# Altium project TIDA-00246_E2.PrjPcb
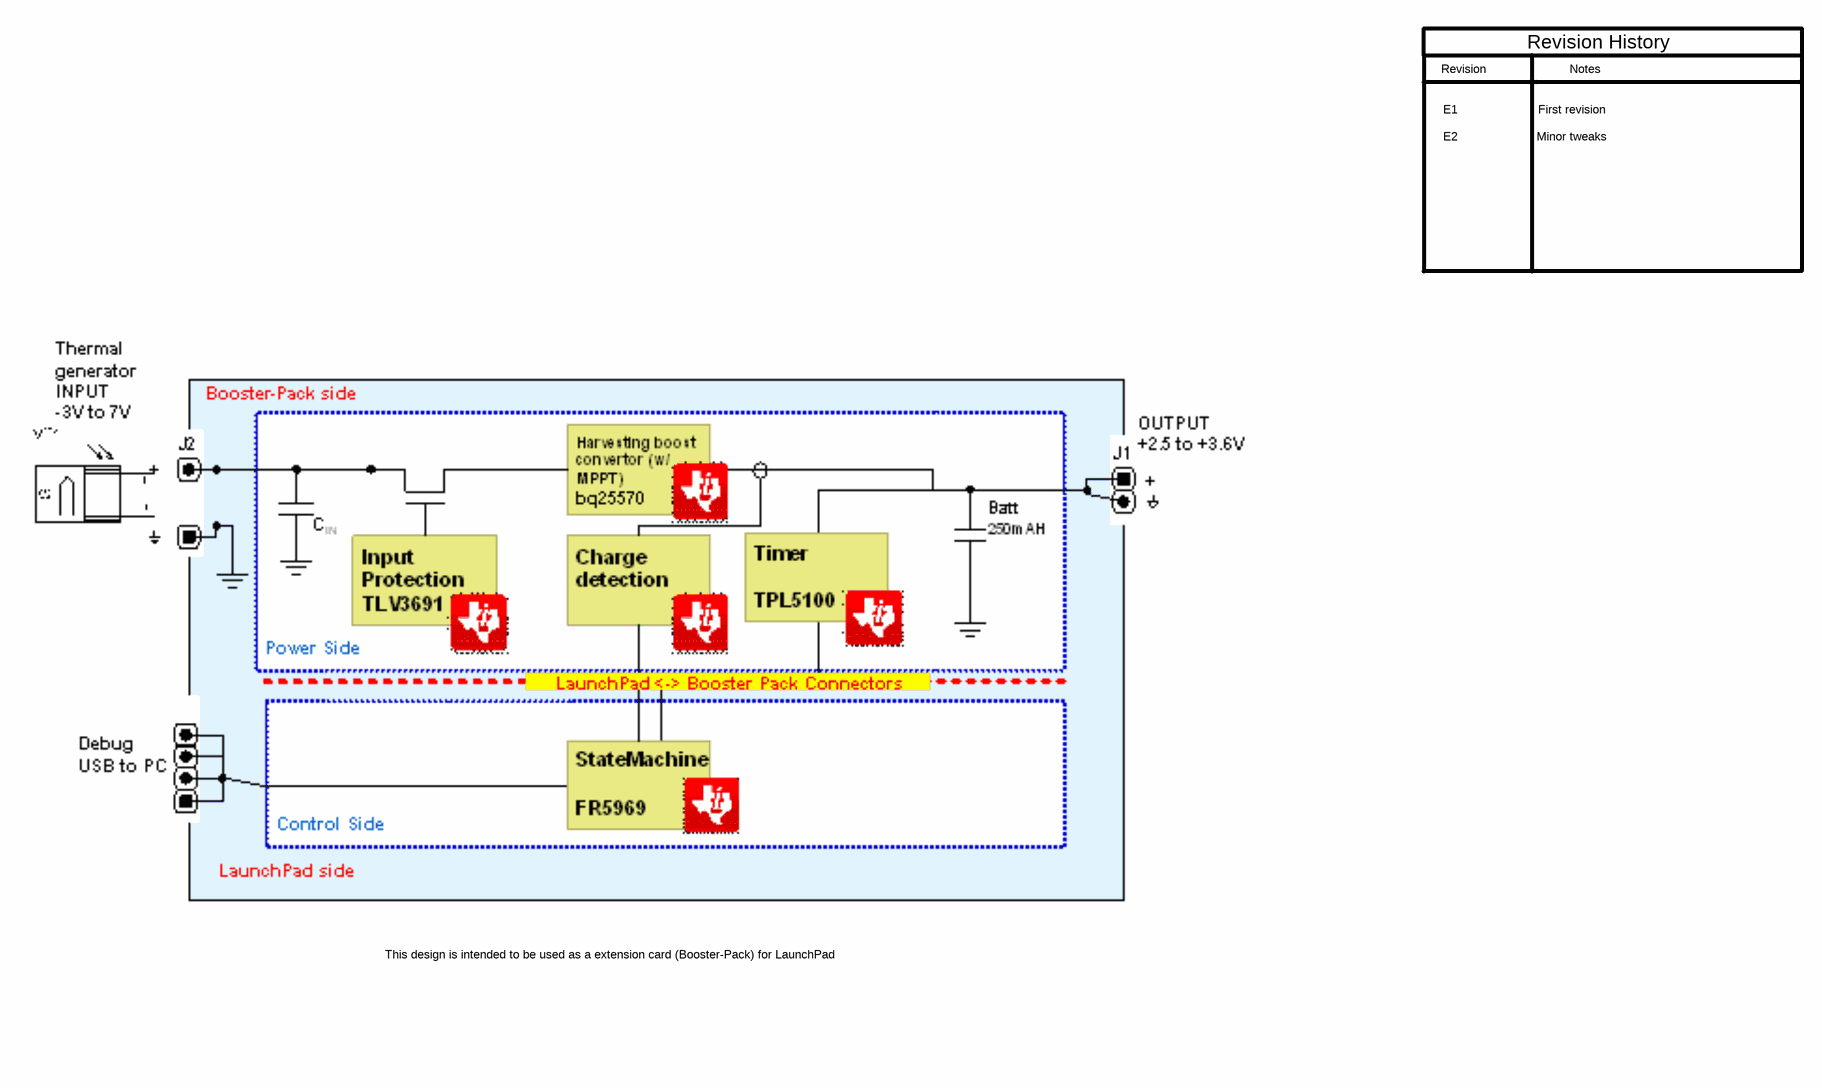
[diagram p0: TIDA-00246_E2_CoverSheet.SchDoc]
TID: TIDA-00246; TechSupport: http://www.ti.com/support; SCH_Rev: E2; PRJ_Title: Generic Energy Harvester Adapter Module for Marlow PowerStrap; PRJ_Number: TIDA-00246; PRJ_Engineer: M. Chevrier; PRJ_Customer: Public Release; PCB_Rev: E2; PCB_Layout: E2: MCV - E1:GCD/KLAK; EVM_Orderable: N/A; CopyrightYear: 2014
4 sheets, 75 parts. Net scope: flat (ports and power ports of the same name join across sheets).
Board file: TIDA-00246_E2_TID.PcbDoc
Sheets:
  TIDA-00246_E2_CoverSheet.SchDoc
  TIDA-00246_E2_Power.SchDoc
  TIDA-00246_E2_BoosterPack.SchDoc
  TIDA-00246_E2_TID_Hardware.SchDoc

## Sheet TIDA-00246_E2_CoverSheet.SchDoc
size 431 x 279 mm; Date: Not shown in title block; ApprovedBy: Not shown in title block; CheckedBy: Not shown in title block; Author: Not shown in title block; CompanyName: Not shown in title block; Engineer: Not shown in title block; Organization: Not shown in title block; Address1: Not shown in title block; Address2: Not shown in title block; Address3: Not shown in title block; Address4: Not shown in title block; DocumentNumber: 1; Revision: Use project parameter SCH_Rev; SheetNumber: 1; SheetTotal: 4; PageSetup: Record=PageOptions¦CenterHorizontal=True¦CenterVertical=True¦PrintScale=1.00¦XCorrection=1.00¦YCorrection=1.00¦PrintKind=0¦BorderSize=5000000¦LeftOffset=0¦BottomOffset=0¦Orientation=2¦PaperLength=1000¦PaperWidth=1000¦Scale=100¦PaperSource=15¦PrintQuality=-3¦MediaType=1¦DitherType=10¦PrintScaleMode=1¦PaperKind=11x17¦PaperIndex=3

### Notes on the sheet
- Revision
- Notes
- Revision History
- E1
- E2
- First revision
- Minor tweaks
- This design is intended to be used as a extension card (Booster-Pack) for LaunchPad

## Sheet TIDA-00246_E2_Power.SchDoc
size 431 x 279 mm; Date: Not shown in title block; ApprovedBy: Not shown in title block; CheckedBy: Not shown in title block; Author: Not shown in title block; CompanyName: Not shown in title block; Engineer: Not shown in title block; Organization: Not shown in title block; Address1: Not shown in title block; Address2: Not shown in title block; Address3: Not shown in title block; Address4: Not shown in title block; DocumentNumber: 2; Revision: Use project parameter SCH_Rev; SheetNumber: 2; SheetTotal: 4; PageSetup: Record=PageOptions¦CenterHorizontal=True¦CenterVertical=True¦PrintScale=1.00¦XCorrection=1.00¦YCorrection=1.00¦PrintKind=0¦BorderSize=5000000¦LeftOffset=0¦BottomOffset=0¦Orientation=2¦PaperLength=1000¦PaperWidth=1000¦Scale=100¦PaperSource=15¦PrintQuality=600¦MediaType=1¦DitherType=10¦PaperKind=Letter¦PrintScaleMode=1
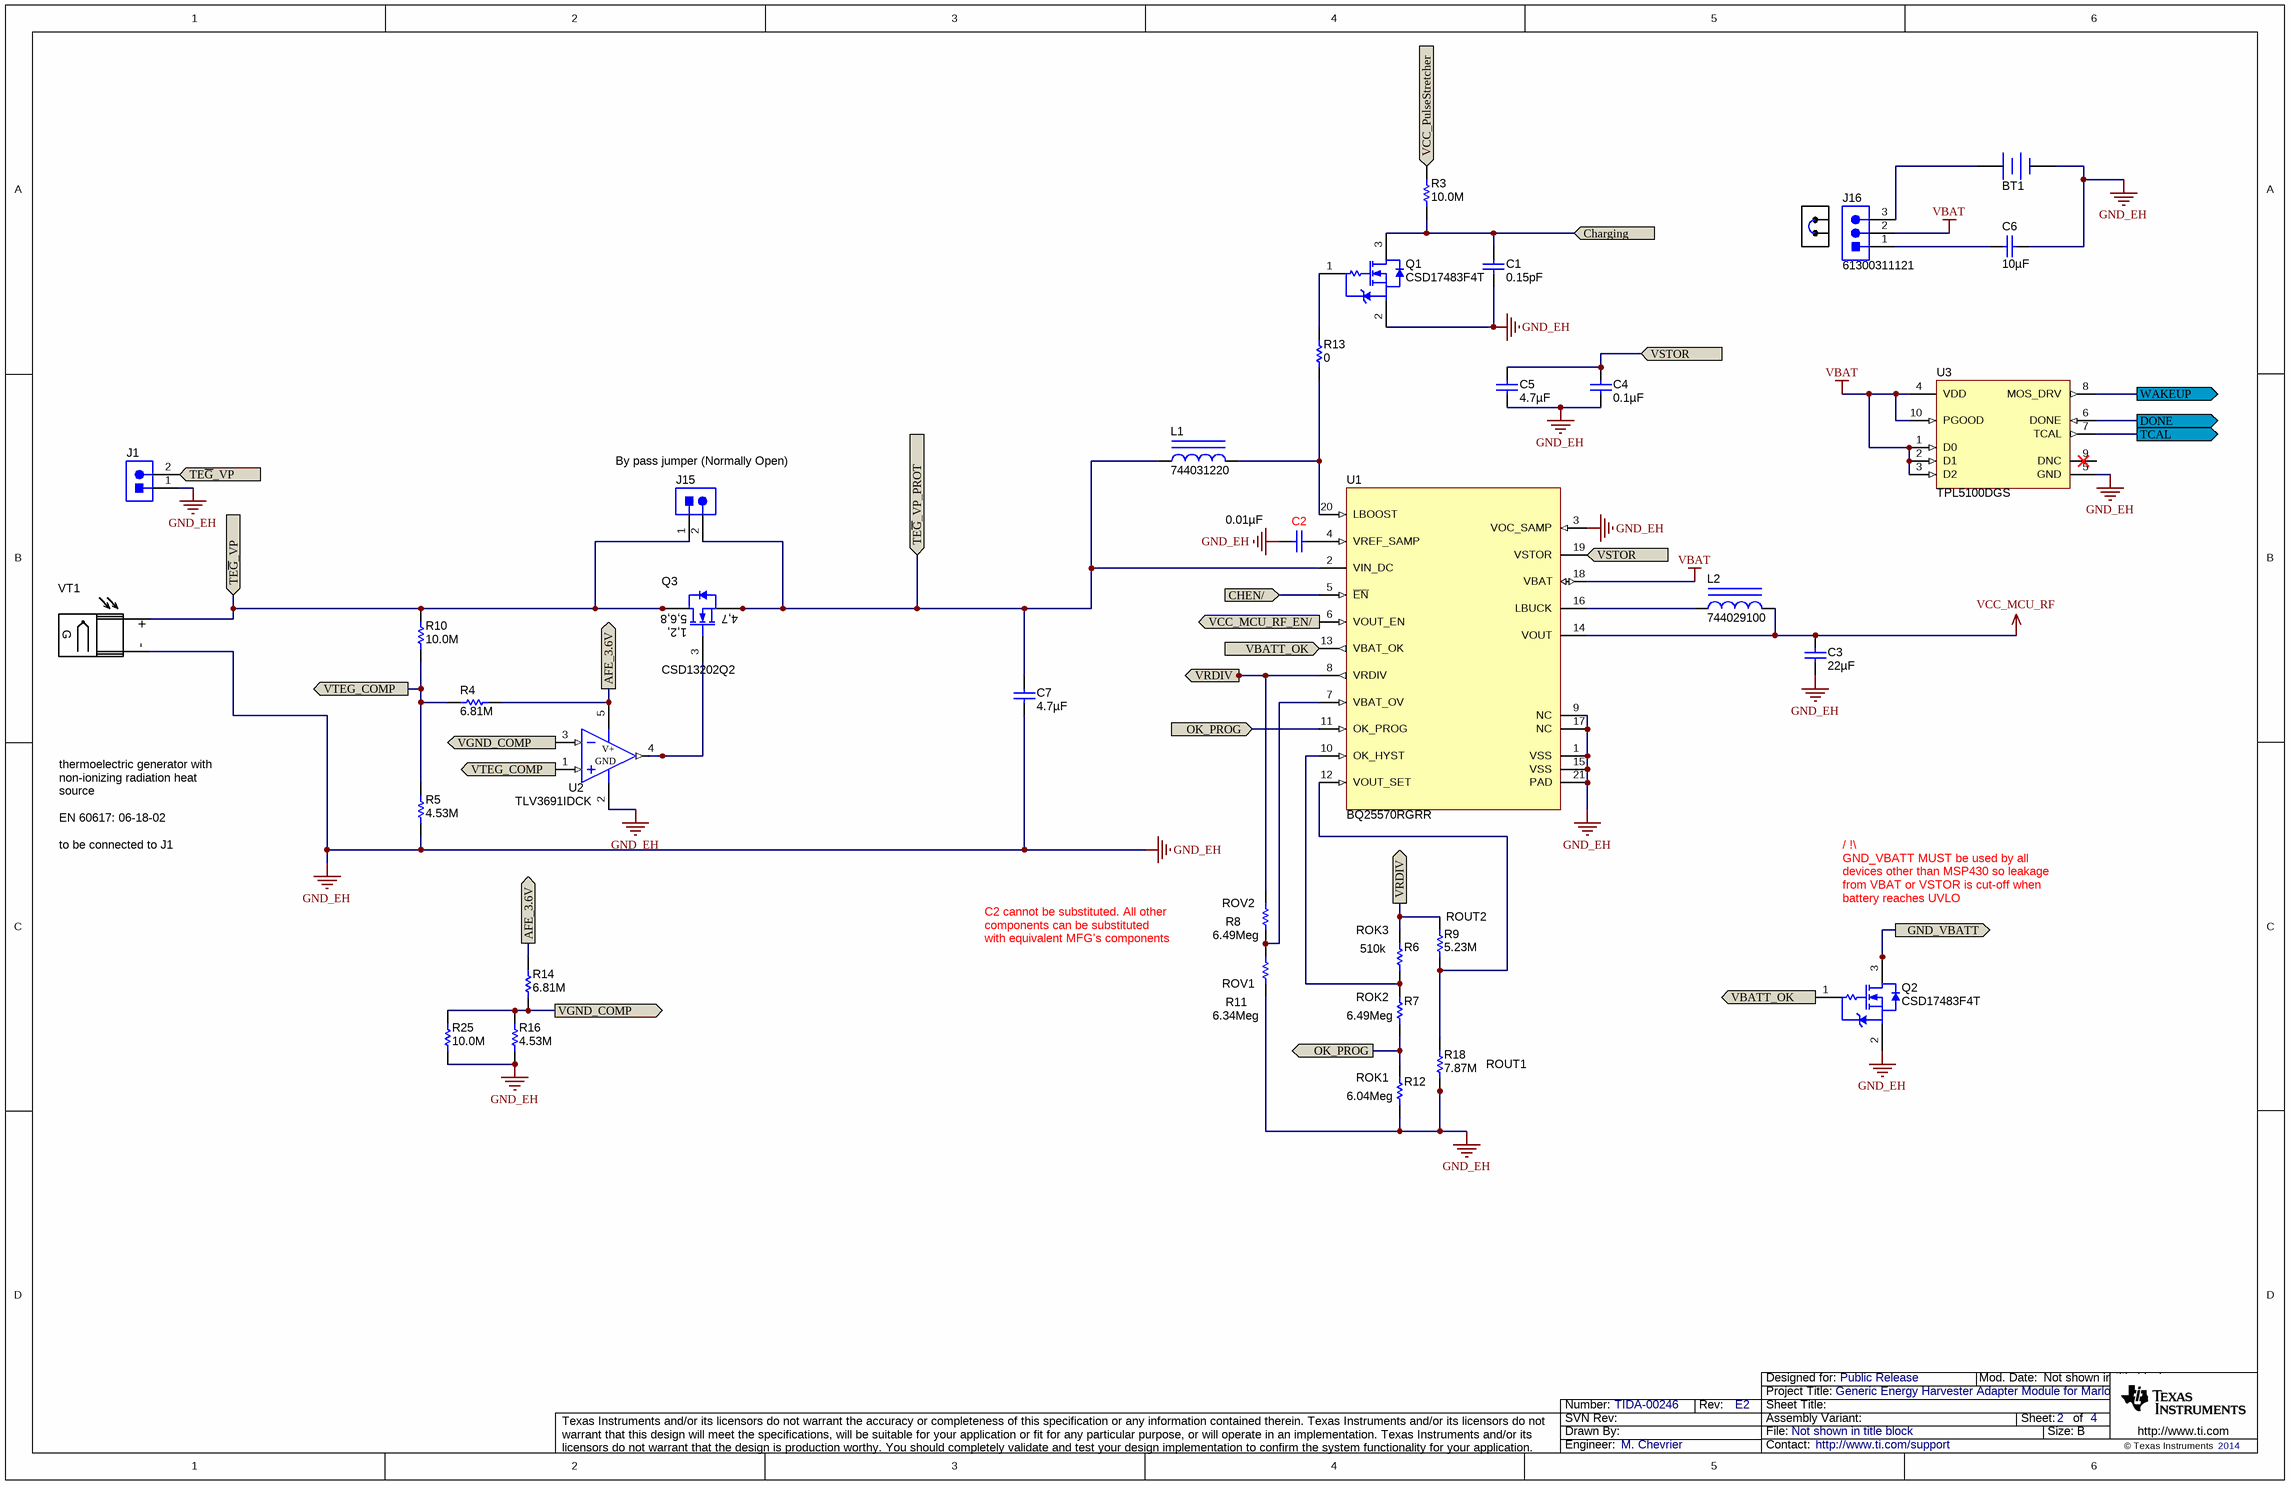
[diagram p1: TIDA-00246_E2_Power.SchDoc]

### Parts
BT1  HLC-1550A/TP  [Tadiran_HLC-1550A_TP]  (value not drawn)
C1  ValueDisplayed: 0.15pF  [0402_70]  (hidden comment: C04ULR15D-6SN-X0T)
C2  ValueDisplayed: 0.01µF  [0603]  (hidden comment: GRM188R71H103KA01D)
C3  ValueDisplayed: 22µF  [0805_HV]  (hidden comment: JMK212BJ226MG-T)
C4  ValueDisplayed: 0.1µF  [0603]  (hidden comment: 06033D104KAT2A)
C5  ValueDisplayed: 4.7µF  [0805_HV]  (hidden comment: LMK212B7475KG-T)
C6  ValueDisplayed: 10µF  [1210]  (hidden comment: 1210YD106KAT2A)
C7  ValueDisplayed: 4.7µF  [0805_HV]  (hidden comment: LMK212B7475KG-T)
J1  61300211121  [WURTH_61300211121]  (value not drawn)
J15  61300211121  [WURTH_61300211121]  (value not drawn)
J16  61300311121  [WURTH_61300311121]
L1  744031220  [WE-TPC-S]
L2  744029100  [WE-TPC_2813]
Q1  CSD17483F4T  [YJC0003A]
Q2  CSD17483F4T  [YJC0003A]
Q3  CSD13202Q2  [TRANS_NexFET_Q2]
R3  ValueDisplayed: 10.0M  [1206]  (hidden comment: CRCW120610M0FKEA)
R4  ValueDisplayed: 6.81M  [1206]  (hidden comment: CRCW12066M81FKEA)
R5  ValueDisplayed: 4.53M  [1206]  (hidden comment: CRCW12064M53FKEA)
R6  value 510k  [0603]  (hidden comment: CRCW0603510KJNEA)
R7  value 6.49Meg  [0603]  (hidden comment: CRCW06036M49FKEA)
R8  value 6.49Meg  [0603]  (hidden comment: CRCW06036M49FKEA)
R9  ValueDisplayed: 5.23M  [0805_HV]  (hidden comment: CRCW08055M23FKEA)
R10  ValueDisplayed: 10.0M  [1206]  (hidden comment: CRCW120610M0FKEA)
R11  value 6.34Meg  [0603]  (hidden comment: CRCW06036M34FKEA)
R12  value 6.04Meg  [0603]  (hidden comment: CRCW06036M04FKEA)
R13  ValueDisplayed: 0  [0805_HV]  (hidden comment: CRCW08050000Z0EA)
R14  ValueDisplayed: 6.81M  [1206]  (hidden comment: CRCW12066M81FKEA)
R16  ValueDisplayed: 4.53M  [1206]  (hidden comment: CRCW12064M53FKEA)
R18  ValueDisplayed: 7.87M  [1206]  (hidden comment: CRCW12067M87FKEA)
R25  ValueDisplayed: 10.0M  [1206]  (hidden comment: CRCW120610M0FKEA)
SH-J11  969102-0000-DA  [SNT-100-BK-G]  (value not drawn)
U1  BQ25570RGRR  [RGR0020A]
U2  TLV3691IDCK  [DCK0005A_N]
U3  TPL5100DGS  [DGS0010A_N]
VT1  N/A  (value not drawn)

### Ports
AFE_3.6V, Charging, CHEN/ (in), DONE (out), GND_VBATT (out), OK_PROG (in), OK_PROG (out), TCAL (out), TE~{G}_VP, TE~{G}_VP_PROT, VBATT_OK (out), VCC_MCU_RF_EN/ (in), VCC_PulseStretcher, VGND_COMP (out), VRDIV, VSTOR, VTEG_COMP (out), WAKEUP (out)

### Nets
GND_EH: BT1.2(-) C1.2 C2.1 C3.2 C4.2 C5.2 C6.1 C7.2 J1.1 Q1.2(S) Q2.2(S) R5.1 R11.2 R12.2 R16.1 R18.1 R25.1 U1.1(VSS) U1.3(VOC_SAMP) U1.9(NC) U1.15(VSS) U1.17(NC) U1.21(PAD) U2.2(GND) U3.5(GND) VT1.2(-)
VBAT: J16.2 U1.18(VBAT) U3.1(D0) U3.2(D1) U3.3(D2) U3.4(VDD) U3.10(PGOOD)
VCC_MCU_RF: C3.1 L2.1 U1.14(VOUT)
AFE_3.6V: R4.2 R14.2 U2.5(V+) ; port AFE_3.6V
Charging: C1.1 Q1.3(D) R3.1 ; port Charging
CHEN/: U1.5(~{EN}) ; port CHEN/
DONE: U3.6(DONE) ; port DONE
GND_VBATT: Q2.3(D) ; port GND_VBATT
OK_PROG: R7.1 R12.1 U1.11(OK_PROG) ; port OK_PROG
TCAL: U3.7(TCAL) ; port TCAL
TE~{G}_VP: J1.2 J15.1 Q3.1(D) Q3.2(D) Q3.5(D) Q3.6(D) Q3.8(D) R10.2 VT1.1(+) ; port TE~{G}_VP
TE~{G}_VP_PROT: C7.1 J15.2 L1.1 Q3.4(S) Q3.7(S) U1.2(VIN_DC) ; port TE~{G}_VP_PROT
VBATT_OK: Q2.1(G) U1.13(VBAT_OK) ; port VBATT_OK
VCC_MCU_RF_EN/: U1.6(VOUT_EN) ; port VCC_MCU_RF_EN/
VCC_PulseStretcher: R3.2 ; port VCC_PulseStretcher
VGND_COMP: R14.1 R16.2 R25.2 U2.3(IN-) ; port VGND_COMP
VRDIV: R6.2 R8.2 R9.2 U1.8(VRDIV) ; port VRDIV
VSTOR: C4.1 C5.1 U1.19(VSTOR) ; port VSTOR
VTEG_COMP: R4.1 R5.2 R10.1 U2.1(IN+) ; port VTEG_COMP
WAKEUP: U3.8(MOS_DRV) ; port WAKEUP
NetBT1_1: BT1.1(+) J16.3
NetC2_2: C2.2 U1.4(VREF_SAMP)
NetC6_2: C6.2 J16.1
NetL1_2: L1.2 R13.1 U1.20(LBOOST)
NetL2_2: L2.2 U1.16(LBUCK)
NetQ1_1: Q1.1(G) R13.2
NetQ3_3: Q3.3(G) U2.4(OUT)
NetR6_1: R6.1 R7.2 U1.10(OK_HYST)
NetR8_1: R8.1 R11.1 U1.7(VBAT_OV)
NetR9_1: R9.1 R18.2 U1.12(VOUT_SET)

Not connected (* = marked no-connect by the designer): U3 9(DNC)

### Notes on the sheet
- (near J15) By pass jumper (Normally Open)
- thermoelectric generator with non-ionizing radiation heat source
  EN 60617: 06-18-02
  to be connected to J1
- (near R8) ROV2
- / !\
  GND_VBATT MUST be used by all devices other than MSP430 so leakage from VBAT or VSTOR is cut-off when battery reaches UVLO
- C2 cannot be substituted. All other components can be substituted with equivalent MFG's components
- (near R6) ROK3
- (near R9) ROUT2
- (near R11) ROV1
- ROK2
- (near R12) ROK1
- (near R18) ROUT1

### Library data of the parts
BT1 = HLC-1550A/TP: Battery, 3.95 V, Axial, TH; Manufacturer: Tadiran Batteries
C1 = C04ULR15D-6SN-X0T: CAP, CERM, 0.15 pF, 200 V, +/- %, X7R, 0402; Manufacturer: Knowles Accoustics; Polarized: N; CompType: Capacitor; Value: 0.15pF; U/M: EA; Cap_F: 0.00000000000015; Value1: Unknown; VDC_V: 200; Value2: 200V; TaMin_C: -55; TaMax_C: 125; Cap_Case: 0402
C2 = GRM188R71H103KA01D: CAP, CERM, 0.01uF, 50V, +/-10%, X7R, 0603; Manufacturer: MuRata; Polarized: N; CompType: Capacitor; U/M: EA; Cap_F: 0.00000001; Tolerance_%: 10; Value1: Unknown; VDC_V: 50; TaMin_C: -55; TaMax_C: 125
C3 = JMK212BJ226MG-T: CAP, CERM, 22uF, 6.3V, +/-20%, X5R, 0805; Manufacturer: Taiyo Yuden; Polarized: N; CompType: Capacitor; U/M: EA; Cap_F: 0.000022; Tolerance_%: 20; Value1: Unknown; VDC_V: 6.3; TaMin_C: -55; TaMax_C: 85; Cap_Case: 0805
C4 = 06033D104KAT2A: CAP, CERM, 0.1uF, 25V, +/-10%, X5R, 0603; Manufacturer: AVX; Polarized: N; CompType: Capacitor; U/M: EA; Cap_F: 0.0000001; Tolerance_%: 10; ESR_Ohm: 0.048; Value1: 0.048 ohm; VDC_V: 25; IRMS_A: 0.53; TaMin_C: -55; TaMax_C: 85
C5 C7 = LMK212B7475KG-T: CAP, CERM, 4.7uF, 10V, +/-10%, X7R, 0805; Manufacturer: Taiyo Yuden; Polarized: N; CompType: Capacitor; U/M: EA; Cap_F: 0.0000047; Tolerance_%: 10; Value1: Unknown; TaMin_C: -55; TaMax_C: 125; Cap_Case: 0805
C6 = 1210YD106KAT2A: CAP, CERM, 10 µF, 16 V, +/- 10%, X5R, 1210; Manufacturer: AVX; Polarized: N; CompType: Capacitor; Value: 10uF; U/M: EA; Cap_F: 0.00001; Tolerance_%: 10; Value1: Unknown; VDC_V: 16; Value2: 16V; TaMin_C: -55; TaMax_C: 85
J1 J15 = 61300211121: Header, 2.54 mm, 2x1, Gold, TH; Manufacturer: Wurth Elektronik eiSos; SymbolCreator: a0412235; U/M: EA
J16 = 61300311121: Header, 2.54 mm, 3x1, Gold, TH; Manufacturer: Wurth Elektronik eiSos; SymbolCreator: a0799628; U/M: EA
L1 = 744031220: Inductor, Shielded Drum Core, Ferrite, 22 µH, 0.36 A, 0.41 ohm, SMD; Manufacturer: Wurth Elektronik eiSos; Value: 22uH; Ind_H: 22.0E-6; ValueDisplayed: 22µH; Imax_A: 0.36; Irms: 0.51A @ 30C rise; Isat: 0.36A @ 35% inductance drop; DCR_ohm: 0.41; Value2: 0.36A
L2 = 744029100: Inductor, Shielded Drum Core, Ferrite, 10 µH, 0.5 A, 0.39 ohm, SMD; Manufacturer: Wurth Elektronik eiSos; Value: 10uH; Ind_H: 10.0E-6; ValueDisplayed: 10µH; Imax_A: 0.5; Irms: 0.75A @ 40C rise; Isat: 0.5A @ 35% inductance drop; DCR_ohm: 0.39; Value2: 0.5A
Q1 Q2 = CSD17483F4T: MOSFET, N/P-CH, 30 V, 1.5 A, 1.0x0.35x0.6mm; Manufacturer: Texas Instruments; Alternate Manufacturer: None; SymbolCreator: a0411947; U/M: EA; ChType: N; Value: 30V; VdsMax_V: 30; Value1: 0.2 ohm; Rdson45_ohm: 0.2; Value2: 1.01 nC; QgTyp_nC: 1.01; Vgs_V: 12; IdsMax_A: 1.5
Q3 = CSD13202Q2: MOSFET, N-CH, 12 V, 14.4 A, SON 2x2mm; Manufacturer: Texas Instruments; Alternate Manufacturer: None; U/M: EA; ChType: N; Value: 12V; VdsMax_V: 12; Value1: 0.0093 ohm; Rdson45_ohm: 0.0093; Value2: 5.1 nC; QgTyp_nC: 5.1; Vgs_V: 8; IdsMax_A: 14.4
R3 R10 R25 = CRCW120610M0FKEA: RES, 10.0 M, 1%, 0.25 W, 1206; Manufacturer: Vishay-Dale; CompType: Resistor; Value: 10.0Meg; Res_ohm: 10000000; Value_Code: 10M0; Tolerance_%: 1; Power_W: 0.25; Value2: 0.25W; VDC_V: 200; TempCo: 100 ppm/C; EIA_Code: E96; U/M: EA
R4 R14 = CRCW12066M81FKEA: RES, 6.81 M, 1%, 0.25 W, 1206; Manufacturer: Vishay-Dale; CompType: Resistor; Value: 6.81Meg; Res_ohm: 6810000; Value_Code: 6M81; Tolerance_%: 1; Power_W: 0.25; Value2: 0.25W; VDC_V: 200; TempCo: 100 ppm/C; EIA_Code: E96; U/M: EA
R5 R16 = CRCW12064M53FKEA: RES, 4.53 M, 1%, 0.25 W, 1206; Manufacturer: Vishay-Dale; CompType: Resistor; Value: 4.53Meg; Res_ohm: 4530000; Value_Code: 4M53; Tolerance_%: 1; Power_W: 0.25; Value2: 0.25W; VDC_V: 200; TempCo: 100 ppm/C; EIA_Code: E96; U/M: EA
R6 = CRCW0603510KJNEA: RES, 510k ohm, 5%, 0.1W, 0603; Manufacturer: Vishay-Dale; CompType: Resistor; Res_ohm: 510000; Tolerance_%: 5; Power_W: 0.1; VDC_V: 75; TempCo: 200 ppm/C; EIA_Code: E24; U/M: EA
R7 R8 = CRCW06036M49FKEA: RES, 6.49Meg ohm, 1%, 0.1W, 0603; Manufacturer: Vishay-Dale; CompType: Resistor; Res_ohm: 6490000; Value_Code: 6M49; Tolerance_%: 1; Power_W: 0.1; VDC_V: 75; TempCo: 100 ppm/C; EIA_Code: E96; U/M: EA
R9 = CRCW08055M23FKEA: RES, 5.23 M, 1%, 0.125 W, 0805; Manufacturer: Vishay-Dale; CompType: Resistor; Value: 5.23Meg; Res_ohm: 5230000; Value_Code: 5M23; Tolerance_%: 1; Power_W: 0.125; Value2: 0.125W; VDC_V: 150; TempCo: 100 ppm/C; EIA_Code: E96; U/M: EA
R11 = CRCW06036M34FKEA: RES, 6.34Meg ohm, 1%, 0.1W, 0603; Manufacturer: Vishay-Dale; CompType: Resistor; Res_ohm: 6340000; Value_Code: 6M34; Tolerance_%: 1; Power_W: 0.1; VDC_V: 75; TempCo: 100 ppm/C; EIA_Code: E96; U/M: EA
R12 = CRCW06036M04FKEA: RES, 6.04Meg ohm, 1%, 0.1W, 0603; Manufacturer: Vishay-Dale; CompType: Resistor; Res_ohm: 6040000; Value_Code: 6M04; Tolerance_%: 1; Power_W: 0.1; VDC_V: 75; TempCo: 100 ppm/C; EIA_Code: E96; U/M: EA
R13 = CRCW08050000Z0EA: RES, 0, 5%, 0.125 W, 0805; Manufacturer: Vishay-Dale; CompType: Resistor; Value: 0; Value_Code: 0000; Tolerance_%: 5; Power_W: 0.125; Value2: 0.125W; VDC_V: 150; TempCo: 200 ppm/C; EIA_Code: E24; U/M: EA
R18 = CRCW12067M87FKEA: RES, 7.87 M, 1%, 0.25 W, 1206; Manufacturer: Vishay-Dale; CompType: Resistor; Value: 7.87Meg; Res_ohm: 7870000; Value_Code: 7M87; Tolerance_%: 1; Power_W: 0.25; Value2: 0.25W; VDC_V: 200; TempCo: 100 ppm/C; EIA_Code: E96; U/M: EA
SH-J11 = 969102-0000-DA: Shunt, 100mil, Gold plated, Black; Manufacturer: 3M; Alternate Manufacturer: Samtec; Value: 1x2; Note: You can "mate" this to a header by matching the designator.  i.e. use SH-J3 for header J3
U1 = BQ25570RGRR: Ultra Low Power Harvester Power Management IC with Boost Charger, and Nano-Powered Buck Converter, RGR0020A; Alternate PartNumber: BQ25570RGRT; Manufacturer: Texas Instruments; SymbolCreator: a0412235; U/M: EA
U2 = TLV3691IDCK: 0.9-V to 6.5-V, Nanopower Comparator, DCK0005A; Manufacturer: Texas Instruments; SymbolCreator: OpAmp IC; CompType: IC; U/M: EA
U3 = TPL5100DGS: Nano Power Programmable Timer, DGS0010A; Manufacturer: Texas Instruments; SymbolCreator: a0411947; CompType: IC; U/M: EA
VT1 = TEG: SymbolCreator: a0411947

## Sheet TIDA-00246_E2_BoosterPack.SchDoc
size 431 x 279 mm; Date: Not shown in title block; ApprovedBy: Not shown in title block; CheckedBy: Not shown in title block; Author: Not shown in title block; CompanyName: Not shown in title block; Engineer: Not shown in title block; Organization: Not shown in title block; Address1: Not shown in title block; Address2: Not shown in title block; Address3: Not shown in title block; Address4: Not shown in title block; DocumentNumber: 3; Revision: Use project parameter SCH_Rev; SheetNumber: 3; SheetTotal: 4; PageSetup: Record=PageOptions¦CenterHorizontal=True¦CenterVertical=True¦PrintScale=1.00¦XCorrection=1.00¦YCorrection=1.00¦PrintKind=0¦BorderSize=5000000¦LeftOffset=0¦BottomOffset=0¦Orientation=2¦PaperLength=1000¦PaperWidth=1000¦Scale=100¦PaperSource=15¦PrintQuality=600¦MediaType=1¦DitherType=10¦PaperKind=Letter¦PrintScaleMode=1
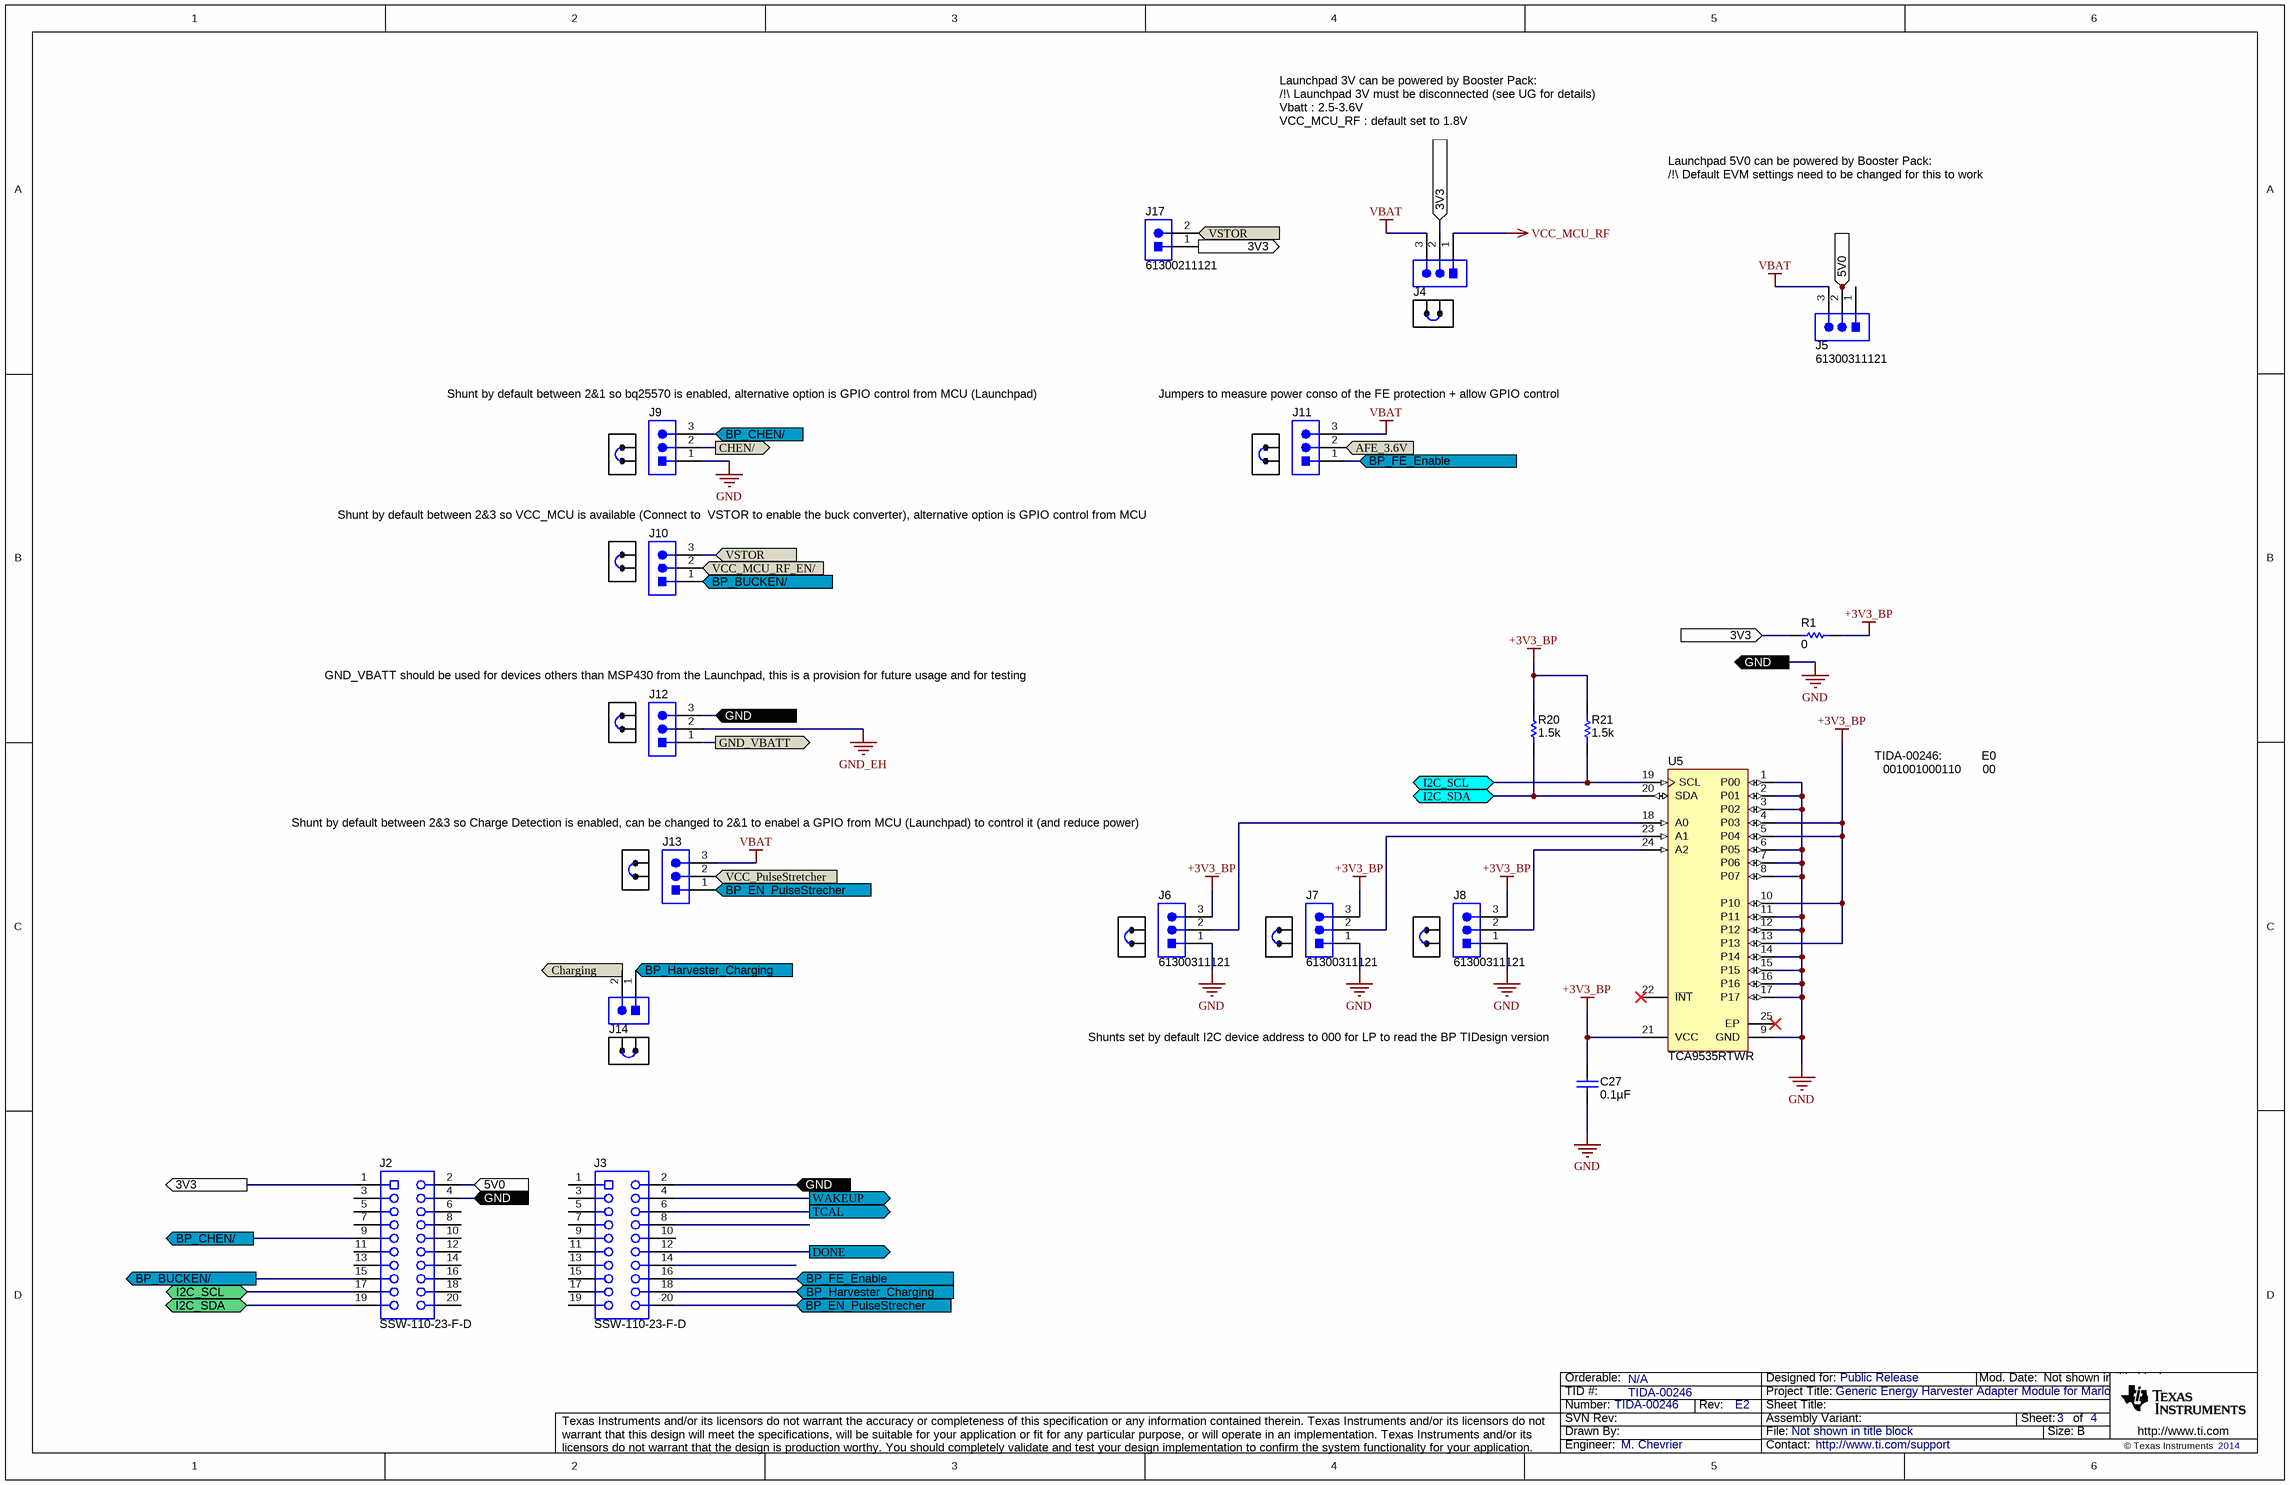
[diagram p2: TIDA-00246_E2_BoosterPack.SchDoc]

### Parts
C27  ValueDisplayed: 0.1µF  [0402]  (hidden comment: GRM155R71A104KA01D)
J2  SSW-110-23-F-D  [CONN_SSW-110-23-F-D]
J3  SSW-110-23-F-D  [CONN_SSW-110-23-F-D]
J4  61300311121  [WURTH_61300311121]  (value not drawn)
J5  61300311121  [WURTH_61300311121]
J6  61300311121  [WURTH_61300311121]
J7  61300311121  [WURTH_61300311121]
J8  61300311121  [WURTH_61300311121]
J9  61300311121  [WURTH_61300311121]  (value not drawn)
J10  61300311121  [WURTH_61300311121]  (value not drawn)
J11  61300311121  [WURTH_61300311121]  (value not drawn)
J12  61300311121  [WURTH_61300311121]  (value not drawn)
J13  61300311121  [WURTH_61300311121]  (value not drawn)
J14  61300211121  [WURTH_61300211121]  (value not drawn)
J17  61300211121  [WURTH_61300211121]
R1  ValueDisplayed: 0  [0805_HV]  (hidden comment: CRCW08050000Z0EA)
R20  value 1.5k  [0402]  (hidden comment: CRCW04021K50JNED)
R21  value 1.5k  [0402]  (hidden comment: CRCW04021K50JNED)
SH-J1  969102-0000-DA  [SNT-100-BK-G]  (value not drawn)
SH-J2  969102-0000-DA  [SNT-100-BK-G]  (value not drawn)
SH-J3  969102-0000-DA  [SNT-100-BK-G]  (value not drawn)
SH-J4  969102-0000-DA  [SNT-100-BK-G]  (value not drawn)
SH-J5  969102-0000-DA  [SNT-100-BK-G]  (value not drawn)
SH-J6  969102-0000-DA  [SNT-100-BK-G]  (value not drawn)
SH-J7  969102-0000-DA  [SNT-100-BK-G]  (value not drawn)
SH-J8  969102-0000-DA  [SNT-100-BK-G]  (value not drawn)
SH-J9  969102-0000-DA  [SNT-100-BK-G]  (value not drawn)
SH-J10  969102-0000-DA  [SNT-100-BK-G]  (value not drawn)
U5  TCA9535RTWR  [RTW0024B]

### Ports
3V3, 5V0, AFE_3.6V (out), BP_BUCKEN/, BP_CHEN/, BP_EN_PulseStrecher, BP_FE_Enable, BP_Harvester_Charging, Charging, CHEN/ (out), DONE (out), GND, GND_VBATT (out), I2C_SCL (bidir), I2C_SDA (bidir), TCAL (out), VCC_MCU_RF_EN/ (out), VCC_PulseStretcher, VSTOR, WAKEUP (out)

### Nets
+3V3_BP: C27.2 J6.3 J7.3 J8.3 R1.1 R20.2 R21.2 U5.4(P03) U5.5(P04) U5.10(P10) U5.13(P13) U5.21(VCC)
GND: C27.1 J2.4 J3.2 J6.1 J7.1 J8.1 J9.1 J12.3 U5.1(P00) U5.2(P01) U5.3(P02) U5.6(P05) U5.7(P06) U5.8(P07) U5.9(GND) U5.11(P11) U5.12(P12) U5.14(P14) U5.15(P15) U5.16(P16) U5.17(P17) ; port GND
GND_EH: J12.2
VBAT: J4.3 J5.3 J11.3 J13.3
VCC_MCU_RF: J4.1
3V3: J2.1 J4.2 J17.1 R1.2 ; port 3V3
5V0: J2.2 J5.2 ; port 5V0
AFE_3.6V: J11.2 ; port AFE_3.6V
BP_BUCKEN/: J2.15 J10.1 ; port BP_BUCKEN/
BP_CHEN/: J2.9 J9.3 ; port BP_CHEN/
BP_EN_PulseStrecher: J3.20 J13.1 ; port BP_EN_PulseStrecher
BP_FE_Enable: J3.16 J11.1 ; port BP_FE_Enable
BP_Harvester_Charging: J3.18 J14.1 ; port BP_Harvester_Charging
Charging: J14.2 ; port Charging
CHEN/: J9.2 ; port CHEN/
DONE: J3.12 ; port DONE
GND_VBATT: J12.1 ; port GND_VBATT
I2C_SCL: J2.17 R21.1 U5.19(SCL) ; port I2C_SCL
I2C_SDA: J2.19 R20.1 U5.20(SDA) ; port I2C_SDA
TCAL: J3.6 ; port TCAL
VCC_MCU_RF_EN/: J10.2 ; port VCC_MCU_RF_EN/
VCC_PulseStretcher: J13.2 ; port VCC_PulseStretcher
VSTOR: J10.3 J17.2 ; port VSTOR
WAKEUP: J3.4 ; port WAKEUP
NetJ6_2: J6.2 U5.18(A0)
NetJ7_2: J7.2 U5.23(A1)
NetJ8_2: J8.2 U5.24(A2)

Not connected (* = marked no-connect by the designer): J2 3 5 6 7 8 10 11 12 13 14 16 18 20; J3 1 3 5 7 8 9 10 11 13 14 15 17 19; J5 1; U5 22(~{INT})* 25(EP)*

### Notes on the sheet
- Launchpad 3V can be powered by Booster Pack:
  /!\ Launchpad 3V must be disconnected (see UG for details)
  Vbatt : 2.5-3.6V
  VCC_MCU_RF : default set to 1.8V
- Launchpad 5V0 can be powered by Booster Pack:
  /!\ Default EVM settings need to be changed for this to work
- Shunt by default between 2&1 so bq25570 is enabled, alternative option is GPIO control from MCU (Launchpad)
- Jumpers to measure power conso of the FE protection + allow GPIO control
- Shunt by default between 2&3 so VCC_MCU is available (Connect to  VSTOR to enable the buck converter), alternative option is GPIO control from MCU
- GND_VBATT should be used for devices others than MSP430 from the Launchpad, this is a provision for future usage and for testing
- TIDA-00246:
- 001001000110
- E0
- 00
- Shunt by default between 2&3 so Charge Detection is enabled, can be changed to 2&1 to enabel a GPIO from MCU (Launchpad) to control it (and reduce power)
- (near C27) Shunts set by default I2C device address to 000 for LP to read the BP TIDesign version

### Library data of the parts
C27 = GRM155R71A104KA01D: CAP, CERM, 0.1uF, 10V, +/-10%, X7R, 0402; Manufacturer: MuRata; Polarized: N; CompType: Capacitor; U/M: EA; Cap_F: 0.0000001; Tolerance_%: 10; Value1: Unknown; TaMin_C: -55; TaMax_C: 125
J2 J3 = SSW-110-23-F-D: Connector, Receptacle, 100mil, 10x2, Gold plated, TH; Manufacturer: Samtec; SymbolCreator: a0412235; U/M: EA
J4-J13 = 61300311121: as J16 on sheet TIDA-00246_E2_Power
J14 J17 = 61300211121: as J1 on sheet TIDA-00246_E2_Power
R1 = CRCW08050000Z0EA: as R13 on sheet TIDA-00246_E2_Power
R20 R21 = CRCW04021K50JNED: RES, 1.5k ohm, 5%, 0.063W, 0402; Manufacturer: Vishay-Dale; CompType: Resistor; Res_ohm: 1500; Value_Code: 1k50; Tolerance_%: 5; Power_W: 0.063; VDC_V: 50; TempCo: 200 ppm/C; EIA_Code: E24; U/M: EA
SH-J1-SH-J10 = 969102-0000-DA: as SH-J11 on sheet TIDA-00246_E2_Power
U5 = TCA9535RTWR: Remote 16-Bit I2C and SMBus, Low-Power I/O Expander with Interrupt Output and Config Register, 1.65 to 5.5 V, -40 to 85 degC, 24-pin QFN (RTW), Green (RoHS & no Sb/Br); Manufacturer: Texas Instruments; Alternate Manufacturer: None; Alternate PartNumber: Equivalent; SubFamily: I2C IO Expander; Interrupt Output: Yes; Max Frequency(kHz): 400; I2C Address: 0100 xxx; # of I/Os: 16

## Sheet TIDA-00246_E2_TID_Hardware.SchDoc
size 431 x 279 mm; Date: Not shown in title block; ApprovedBy: Not shown in title block; CheckedBy: Not shown in title block; Author: Not shown in title block; CompanyName: Not shown in title block; Engineer: Not shown in title block; Organization: Not shown in title block; Address1: Not shown in title block; Address2: Not shown in title block; Address3: Not shown in title block; Address4: Not shown in title block; DocumentNumber: 4; Revision: Use project parameter SCH_Rev; SheetNumber: 4; SheetTotal: 4; PageSetup: Record=PageOptions¦CenterHorizontal=True¦CenterVertical=True¦PrintScale=1.00¦XCorrection=1.00¦YCorrection=1.00¦PrintKind=0¦BorderSize=5000000¦LeftOffset=0¦BottomOffset=0¦Orientation=2¦PaperLength=1000¦PaperWidth=1000¦Scale=100¦PaperSource=15¦PrintQuality=600¦MediaType=1¦DitherType=10¦PaperKind=Letter¦PrintScaleMode=1
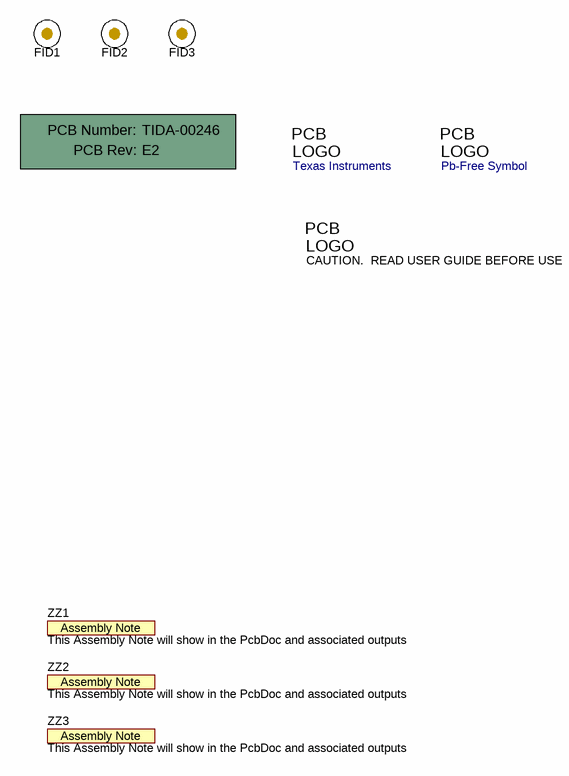
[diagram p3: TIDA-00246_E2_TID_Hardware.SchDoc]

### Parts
!PCB1  Printed Circuit Board  (value not drawn)  (mechanical)
FID1  Fiducial  [Fiducial10-20]  (value not drawn)
FID2  Fiducial  [Fiducial10-20]  (value not drawn)
FID3  Fiducial  [Fiducial10-20]  (value not drawn)
Logo1  Texas Instruments  [TI_Stacked_SolderMask_Small]  (no BOM)
Logo2  Pb-Free Symbol  [Pb-Free_Overlay_Small]  (no BOM)
Read_UG_!  CAUTION.  READ USER GUIDE BEFORE USE  [IEC_Caution_Small]  (no BOM)
ZZ1  This Assembly Note will show in the PcbDoc and associated outputs  [AssemblyNote]  (no BOM)
ZZ2  This Assembly Note will show in the PcbDoc and associated outputs  [AssemblyNote]  (no BOM)
ZZ3  This Assembly Note will show in the PcbDoc and associated outputs  [AssemblyNote]  (no BOM)

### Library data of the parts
!PCB1 = PCB: Manufacturer: Any; PartNumber: TIDA-00246; SymbolCreator: a0412235
FID1-FID3 = Fiducial: Fiducial mark.  There is nothing to buy or mount.; SymbolCreator: codlsc
Logo1 = TI_Logo: Texas Instrument Corporate Signature; SymbolCreator: a0412235
Logo2 = Pb-Free: SymbolCreator: a0412235
Read_UG_! = IEC_Caution: IEC 61010-1 Caution Warning; SymbolCreator: a0412235
ZZ1-ZZ3 = AssemblyNote: SymbolCreator: codlsc

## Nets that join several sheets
GND_EH: TIDA-00246_E2_Power (26 pins), TIDA-00246_E2_BoosterPack (J12.2)
VBAT: TIDA-00246_E2_Power (7 pins), TIDA-00246_E2_BoosterPack (J4.3 J5.3 J11.3 J13.3)
VCC_MCU_RF: TIDA-00246_E2_Power (C3.1 L2.1 U1.14), TIDA-00246_E2_BoosterPack (J4.1)
AFE_3.6V: TIDA-00246_E2_Power (R4.2 R14.2 U2.5), TIDA-00246_E2_BoosterPack (J11.2)
Charging: TIDA-00246_E2_Power (C1.1 Q1.3 R3.1), TIDA-00246_E2_BoosterPack (J14.2)
CHEN/: TIDA-00246_E2_Power (U1.5), TIDA-00246_E2_BoosterPack (J9.2)
DONE: TIDA-00246_E2_Power (U3.6), TIDA-00246_E2_BoosterPack (J3.12)
GND_VBATT: TIDA-00246_E2_Power (Q2.3), TIDA-00246_E2_BoosterPack (J12.1)
TCAL: TIDA-00246_E2_Power (U3.7), TIDA-00246_E2_BoosterPack (J3.6)
VCC_MCU_RF_EN/: TIDA-00246_E2_Power (U1.6), TIDA-00246_E2_BoosterPack (J10.2)
VCC_PulseStretcher: TIDA-00246_E2_Power (R3.2), TIDA-00246_E2_BoosterPack (J13.2)
VSTOR: TIDA-00246_E2_Power (C4.1 C5.1 U1.19), TIDA-00246_E2_BoosterPack (J10.3 J17.2)
WAKEUP: TIDA-00246_E2_Power (U3.8), TIDA-00246_E2_BoosterPack (J3.4)

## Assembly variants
001: not fitted FID1 FID2 FID3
